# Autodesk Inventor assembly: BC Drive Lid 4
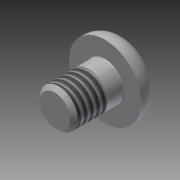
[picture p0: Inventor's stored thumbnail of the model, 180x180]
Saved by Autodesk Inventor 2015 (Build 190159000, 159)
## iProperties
Created: 2007-02
Part Number: BC Drive Lid 4
Document SubType Name: Assembly
Designer: Autodesk, Inc.
Mass: 1.89148 g
Surface Area: 2.92112 cm^2
Volume: 0.240646 cm^3
Density: 7.86 g/cm^3
ClientObjectVersion: 1
Author: Autodesk, Inc.
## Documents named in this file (2)
- C:\Users\Public\Documents\Autodesk\Inventor 2015\Samples\Models\Assemblies\Blower\Blower\Design Accelerator\BC Drive Lid 31.iam
- C:\Users\Public\Documents\Autodesk\Inventor 2015\Samples\Standard Parts\en-US\ANSI B18.3(03)\ANSI B18.3 - 10-32 UNF - UNF - 0.25(1).ipt
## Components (1 placed, 1 different names)
1. ANSI B18.3 - No. 10-32 - 1/4:1
